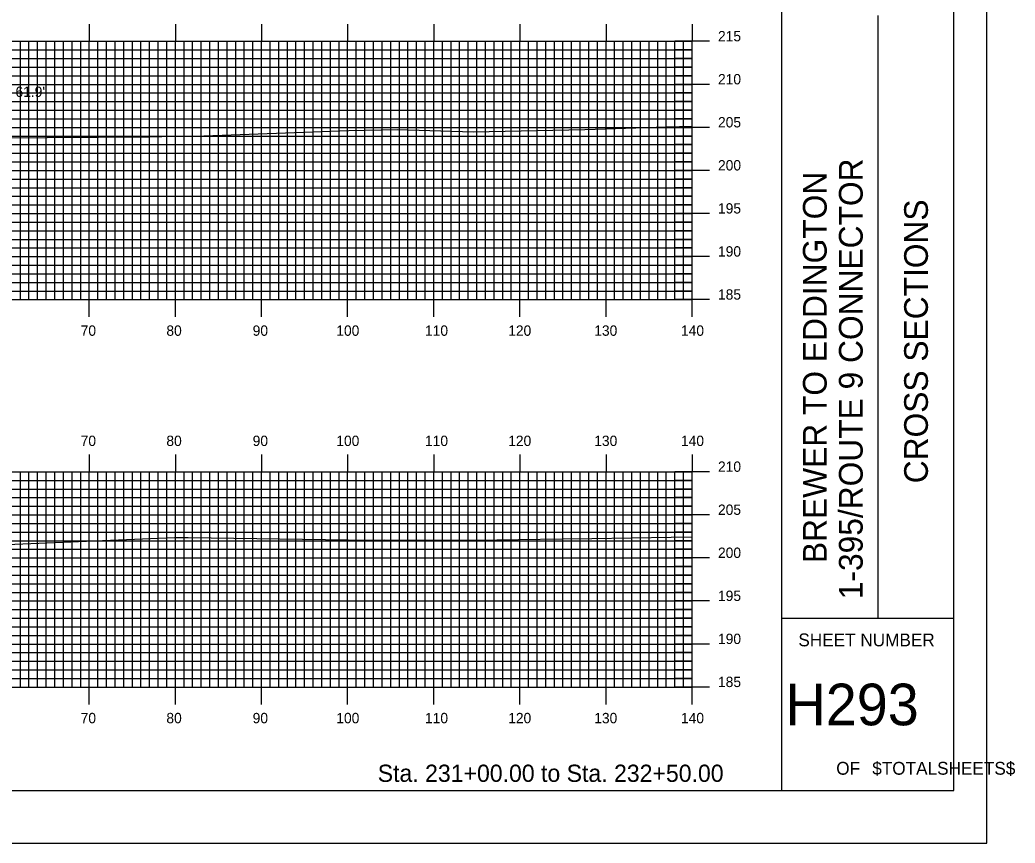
# Model space of a CAD drawing. Extents: x 1799568 to 1799912, y 442591 to 442811.
# Drawn here: x 1799796 to 1799911.5, y 442590.5 to 442686.2 of the extents above; entities that cross this region are included whole.
import ezdxf

# ---------------------------------------------------------------- set-up
doc = ezdxf.new("R2010")
doc.units = 0
for name, color, linetype in [('BORDER', 7, 'Continuous'), ('D_Text_Standard', 7, 'Continuous'), ('H_V ANNOTATION', 7, 'Continuous'), ('MAJOR', 7, 'Continuous'), ('MINOR', 7, 'Continuous'), ('PLOT BOUNDARY', 7, 'Continuous'), ('S_Roadway_Centerline', 7, 'Continuous')]:
    doc.layers.add(name, color=color, linetype=linetype)

msp = doc.modelspace()

# ---------------------------------------------------------------- linework, layer by layer
at = {"layer": 'BORDER'}
for p, q in [((1799884.41, 442596.67), (1799884.41, 442806.67)), ((1799895.59, 442616.67), (1799895.59, 442686.67)), ((1799884.41, 442616.67), (1799904.41, 442616.67))]:
    msp.add_line(p, q, dxfattribs=at)
msp.add_lwpolyline([(1799584.41, 442596.67), (1799904.41, 442596.67), (1799904.41, 442806.67), (1799584.41, 442806.67)], close=True, dxfattribs=at)
at = {"layer": 'MAJOR'}
for p, q in [((1799804.01, 442685.67), (1799804.01, 442683.67)), ((1799814.01, 442685.67), (1799814.01, 442683.67)), ((1799824.01, 442685.67), (1799824.01, 442683.67)), ((1799834.01, 442685.67), (1799834.01, 442683.67)), ((1799844.01, 442685.67), (1799844.01, 442683.67)), ((1799854.01, 442685.67), (1799854.01, 442683.67)), ((1799864.01, 442685.67), (1799864.01, 442683.67)), ((1799874.01, 442685.67), (1799874.01, 442683.67)), ((1799594.01, 442683.67), (1799874.01, 442683.67)), ((1799594.01, 442683.67), (1799874.01, 442683.67)), ((1799804.01, 442653.67), (1799804.01, 442683.67)), ((1799814.01, 442653.67), (1799814.01, 442683.67)), ((1799824.01, 442653.67), (1799824.01, 442683.67)), ((1799834.01, 442653.67), (1799834.01, 442683.67)), ((1799844.01, 442653.67), (1799844.01, 442683.67)), ((1799854.01, 442653.67), (1799854.01, 442683.67)), ((1799864.01, 442653.67), (1799864.01, 442683.67)), ((1799876.01, 442683.67), (1799872.01, 442683.67)), ((1799874.01, 442653.67), (1799874.01, 442683.67)), ((1799874.01, 442653.67), (1799874.01, 442683.67)), ((1799594.01, 442678.67), (1799874.01, 442678.67)), ((1799876.01, 442678.67), (1799872.01, 442678.67)), ((1799594.01, 442673.67), (1799874.01, 442673.67)), ((1799876.01, 442673.67), (1799872.01, 442673.67)), ((1799594.01, 442668.67), (1799874.01, 442668.67)), ((1799876.01, 442668.67), (1799872.01, 442668.67)), ((1799594.01, 442663.67), (1799874.01, 442663.67)), ((1799876.01, 442663.67), (1799872.01, 442663.67)), ((1799594.01, 442658.67), (1799874.01, 442658.67)), ((1799876.01, 442658.67), (1799872.01, 442658.67)), ((1799594.01, 442653.67), (1799874.01, 442653.67)), ((1799594.01, 442653.67), (1799874.01, 442653.67)), ((1799804.01, 442651.66), (1799804.01, 442653.67)), ((1799814.01, 442651.66), (1799814.01, 442653.67)), ((1799824.01, 442651.66), (1799824.01, 442653.67)), ((1799834.01, 442651.66), (1799834.01, 442653.67)), ((1799844.01, 442651.66), (1799844.01, 442653.67)), ((1799854.01, 442651.66), (1799854.01, 442653.67)), ((1799864.01, 442651.66), (1799864.01, 442653.67)), ((1799876.01, 442653.67), (1799872.01, 442653.67)), ((1799874.01, 442651.66), (1799874.01, 442653.67)), ((1799804.01, 442635.67), (1799804.01, 442633.67)), ((1799814.01, 442635.67), (1799814.01, 442633.67)), ((1799824.01, 442635.67), (1799824.01, 442633.67)), ((1799834.01, 442635.67), (1799834.01, 442633.67)), ((1799844.01, 442635.67), (1799844.01, 442633.67)), ((1799854.01, 442635.67), (1799854.01, 442633.67)), ((1799864.01, 442635.67), (1799864.01, 442633.67)), ((1799874.01, 442635.67), (1799874.01, 442633.67)), ((1799594.01, 442633.67), (1799874.01, 442633.67)), ((1799594.01, 442633.67), (1799874.01, 442633.67)), ((1799804.01, 442608.67), (1799804.01, 442633.67)), ((1799814.01, 442608.67), (1799814.01, 442633.67)), ((1799824.01, 442608.67), (1799824.01, 442633.67)), ((1799834.01, 442608.67), (1799834.01, 442633.67)), ((1799844.01, 442608.67), (1799844.01, 442633.67)), ((1799854.01, 442608.67), (1799854.01, 442633.67)), ((1799864.01, 442608.67), (1799864.01, 442633.67)), ((1799876.01, 442633.67), (1799872.01, 442633.67)), ((1799874.01, 442608.67), (1799874.01, 442633.67)), ((1799874.01, 442608.67), (1799874.01, 442633.67)), ((1799594.01, 442628.67), (1799874.01, 442628.67)), ((1799876.01, 442628.67), (1799872.01, 442628.67)), ((1799594.01, 442623.67), (1799874.01, 442623.67)), ((1799876.01, 442623.67), (1799872.01, 442623.67)), ((1799594.01, 442618.67), (1799874.01, 442618.67)), ((1799876.01, 442618.67), (1799872.01, 442618.67)), ((1799594.01, 442613.67), (1799874.01, 442613.67)), ((1799876.01, 442613.67), (1799872.01, 442613.67)), ((1799594.01, 442608.67), (1799874.01, 442608.67)), ((1799594.01, 442608.67), (1799874.01, 442608.67)), ((1799804.01, 442606.66), (1799804.01, 442608.67)), ((1799814.01, 442606.66), (1799814.01, 442608.67)), ((1799824.01, 442606.66), (1799824.01, 442608.67)), ((1799834.01, 442606.66), (1799834.01, 442608.67)), ((1799844.01, 442606.66), (1799844.01, 442608.67)), ((1799854.01, 442606.66), (1799854.01, 442608.67)), ((1799864.01, 442606.66), (1799864.01, 442608.67)), ((1799876.01, 442608.67), (1799872.01, 442608.67)), ((1799874.01, 442606.66), (1799874.01, 442608.67))]:
    msp.add_line(p, q, dxfattribs=at)
at = {"layer": 'MINOR'}
for p, q in [((1799796.01, 442653.67), (1799796.01, 442683.67)), ((1799797.01, 442653.67), (1799797.01, 442683.67)), ((1799798.01, 442653.67), (1799798.01, 442683.67)), ((1799799.01, 442653.67), (1799799.01, 442683.67)), ((1799800.01, 442653.67), (1799800.01, 442683.67)), ((1799801.01, 442653.67), (1799801.01, 442683.67)), ((1799802.01, 442653.67), (1799802.01, 442683.67)), ((1799803.01, 442653.67), (1799803.01, 442683.67)), ((1799805.01, 442653.67), (1799805.01, 442683.67)), ((1799806.01, 442653.67), (1799806.01, 442683.67)), ((1799807.01, 442653.67), (1799807.01, 442683.67)), ((1799808.01, 442653.67), (1799808.01, 442683.67)), ((1799809.01, 442653.67), (1799809.01, 442683.67)), ((1799810.01, 442653.67), (1799810.01, 442683.67)), ((1799811.01, 442653.67), (1799811.01, 442683.67)), ((1799812.01, 442653.67), (1799812.01, 442683.67)), ((1799813.01, 442653.67), (1799813.01, 442683.67)), ((1799815.01, 442653.67), (1799815.01, 442683.67)), ((1799816.01, 442653.67), (1799816.01, 442683.67)), ((1799817.01, 442653.67), (1799817.01, 442683.67)), ((1799818.01, 442653.67), (1799818.01, 442683.67)), ((1799819.01, 442653.67), (1799819.01, 442683.67)), ((1799820.01, 442653.67), (1799820.01, 442683.67)), ((1799821.01, 442653.67), (1799821.01, 442683.67)), ((1799822.01, 442653.67), (1799822.01, 442683.67)), ((1799823.01, 442653.67), (1799823.01, 442683.67)), ((1799825.01, 442653.67), (1799825.01, 442683.67)), ((1799826.01, 442653.67), (1799826.01, 442683.67)), ((1799827.01, 442653.67), (1799827.01, 442683.67)), ((1799828.01, 442653.67), (1799828.01, 442683.67)), ((1799829.01, 442653.67), (1799829.01, 442683.67)), ((1799830.01, 442653.67), (1799830.01, 442683.67)), ((1799831.01, 442653.67), (1799831.01, 442683.67)), ((1799832.01, 442653.67), (1799832.01, 442683.67)), ((1799833.01, 442653.67), (1799833.01, 442683.67)), ((1799835.01, 442653.67), (1799835.01, 442683.67)), ((1799836.01, 442653.67), (1799836.01, 442683.67)), ((1799837.01, 442653.67), (1799837.01, 442683.67)), ((1799838.01, 442653.67), (1799838.01, 442683.67)), ((1799839.01, 442653.67), (1799839.01, 442683.67)), ((1799840.01, 442653.67), (1799840.01, 442683.67)), ((1799841.01, 442653.67), (1799841.01, 442683.67)), ((1799842.01, 442653.67), (1799842.01, 442683.67)), ((1799843.01, 442653.67), (1799843.01, 442683.67)), ((1799845.01, 442653.67), (1799845.01, 442683.67)), ((1799846.01, 442653.67), (1799846.01, 442683.67)), ((1799847.01, 442653.67), (1799847.01, 442683.67)), ((1799848.01, 442653.67), (1799848.01, 442683.67)), ((1799849.01, 442653.67), (1799849.01, 442683.67)), ((1799850.01, 442653.67), (1799850.01, 442683.67)), ((1799851.01, 442653.67), (1799851.01, 442683.67)), ((1799852.01, 442653.67), (1799852.01, 442683.67)), ((1799853.01, 442653.67), (1799853.01, 442683.67)), ((1799855.01, 442653.67), (1799855.01, 442683.67)), ((1799856.01, 442653.67), (1799856.01, 442683.67)), ((1799857.01, 442653.67), (1799857.01, 442683.67)), ((1799858.01, 442653.67), (1799858.01, 442683.67)), ((1799859.01, 442653.67), (1799859.01, 442683.67)), ((1799860.01, 442653.67), (1799860.01, 442683.67)), ((1799861.01, 442653.67), (1799861.01, 442683.67)), ((1799862.01, 442653.67), (1799862.01, 442683.67)), ((1799863.01, 442653.67), (1799863.01, 442683.67)), ((1799865.01, 442653.67), (1799865.01, 442683.67)), ((1799866.01, 442653.67), (1799866.01, 442683.67)), ((1799867.01, 442653.67), (1799867.01, 442683.67)), ((1799868.01, 442653.67), (1799868.01, 442683.67)), ((1799869.01, 442653.67), (1799869.01, 442683.67)), ((1799870.01, 442653.67), (1799870.01, 442683.67)), ((1799871.01, 442653.67), (1799871.01, 442683.67)), ((1799872.01, 442653.67), (1799872.01, 442683.67)), ((1799873.01, 442653.67), (1799873.01, 442683.67)), ((1799594.01, 442682.67), (1799874.01, 442682.67)), ((1799874.01, 442682.67), (1799872.01, 442682.67)), ((1799594.01, 442681.67), (1799874.01, 442681.67)), ((1799874.01, 442681.67), (1799872.01, 442681.67)), ((1799594.01, 442680.67), (1799874.01, 442680.67)), ((1799874.01, 442680.67), (1799872.01, 442680.67)), ((1799594.01, 442679.67), (1799874.01, 442679.67)), ((1799874.01, 442679.67), (1799872.01, 442679.67)), ((1799594.01, 442677.67), (1799874.01, 442677.67)), ((1799594.01, 442676.67), (1799874.01, 442676.67)), ((1799874.01, 442677.67), (1799872.01, 442677.67)), ((1799874.01, 442676.67), (1799872.01, 442676.67)), ((1799594.01, 442675.67), (1799874.01, 442675.67)), ((1799874.01, 442675.67), (1799872.01, 442675.67)), ((1799594.01, 442674.67), (1799874.01, 442674.67)), ((1799874.01, 442674.67), (1799872.01, 442674.67)), ((1799594.01, 442672.67), (1799874.01, 442672.67)), ((1799874.01, 442672.67), (1799872.01, 442672.67)), ((1799594.01, 442671.67), (1799874.01, 442671.67)), ((1799874.01, 442671.67), (1799872.01, 442671.67)), ((1799594.01, 442670.67), (1799874.01, 442670.67)), ((1799874.01, 442670.67), (1799872.01, 442670.67)), ((1799594.01, 442669.67), (1799874.01, 442669.67)), ((1799874.01, 442669.67), (1799872.01, 442669.67)), ((1799594.01, 442667.67), (1799874.01, 442667.67)), ((1799874.01, 442667.67), (1799872.01, 442667.67)), ((1799594.01, 442666.67), (1799874.01, 442666.67)), ((1799874.01, 442666.67), (1799872.01, 442666.67)), ((1799594.01, 442665.67), (1799874.01, 442665.67)), ((1799874.01, 442665.67), (1799872.01, 442665.67)), ((1799594.01, 442664.67), (1799874.01, 442664.67)), ((1799874.01, 442664.67), (1799872.01, 442664.67)), ((1799594.01, 442662.67), (1799874.01, 442662.67)), ((1799594.01, 442661.67), (1799874.01, 442661.67)), ((1799874.01, 442662.67), (1799872.01, 442662.67)), ((1799874.01, 442661.67), (1799872.01, 442661.67)), ((1799594.01, 442660.67), (1799874.01, 442660.67)), ((1799874.01, 442660.67), (1799872.01, 442660.67)), ((1799594.01, 442659.67), (1799874.01, 442659.67)), ((1799874.01, 442659.67), (1799872.01, 442659.67)), ((1799594.01, 442657.67), (1799874.01, 442657.67)), ((1799874.01, 442657.67), (1799872.01, 442657.67)), ((1799594.01, 442656.67), (1799874.01, 442656.67)), ((1799874.01, 442656.67), (1799872.01, 442656.67)), ((1799594.01, 442655.67), (1799874.01, 442655.67)), ((1799874.01, 442655.67), (1799872.01, 442655.67)), ((1799594.01, 442654.67), (1799874.01, 442654.67)), ((1799874.01, 442654.67), (1799872.01, 442654.67)), ((1799796.01, 442608.67), (1799796.01, 442633.67)), ((1799797.01, 442608.67), (1799797.01, 442633.67)), ((1799798.01, 442608.67), (1799798.01, 442633.67)), ((1799799.01, 442608.67), (1799799.01, 442633.67)), ((1799800.01, 442608.67), (1799800.01, 442633.67)), ((1799801.01, 442608.67), (1799801.01, 442633.67)), ((1799802.01, 442608.67), (1799802.01, 442633.67)), ((1799803.01, 442608.67), (1799803.01, 442633.67)), ((1799805.01, 442608.67), (1799805.01, 442633.67)), ((1799806.01, 442608.67), (1799806.01, 442633.67)), ((1799807.01, 442608.67), (1799807.01, 442633.67)), ((1799808.01, 442608.67), (1799808.01, 442633.67)), ((1799809.01, 442608.67), (1799809.01, 442633.67)), ((1799810.01, 442608.67), (1799810.01, 442633.67)), ((1799811.01, 442608.67), (1799811.01, 442633.67)), ((1799812.01, 442608.67), (1799812.01, 442633.67)), ((1799813.01, 442608.67), (1799813.01, 442633.67)), ((1799815.01, 442608.67), (1799815.01, 442633.67)), ((1799816.01, 442608.67), (1799816.01, 442633.67)), ((1799817.01, 442608.67), (1799817.01, 442633.67)), ((1799818.01, 442608.67), (1799818.01, 442633.67)), ((1799819.01, 442608.67), (1799819.01, 442633.67)), ((1799820.01, 442608.67), (1799820.01, 442633.67)), ((1799821.01, 442608.67), (1799821.01, 442633.67)), ((1799822.01, 442608.67), (1799822.01, 442633.67)), ((1799823.01, 442608.67), (1799823.01, 442633.67)), ((1799825.01, 442608.67), (1799825.01, 442633.67)), ((1799826.01, 442608.67), (1799826.01, 442633.67)), ((1799827.01, 442608.67), (1799827.01, 442633.67)), ((1799828.01, 442608.67), (1799828.01, 442633.67)), ((1799829.01, 442608.67), (1799829.01, 442633.67)), ((1799830.01, 442608.67), (1799830.01, 442633.67)), ((1799831.01, 442608.67), (1799831.01, 442633.67)), ((1799832.01, 442608.67), (1799832.01, 442633.67)), ((1799833.01, 442608.67), (1799833.01, 442633.67)), ((1799835.01, 442608.67), (1799835.01, 442633.67)), ((1799836.01, 442608.67), (1799836.01, 442633.67)), ((1799837.01, 442608.67), (1799837.01, 442633.67)), ((1799838.01, 442608.67), (1799838.01, 442633.67)), ((1799839.01, 442608.67), (1799839.01, 442633.67)), ((1799840.01, 442608.67), (1799840.01, 442633.67)), ((1799841.01, 442608.67), (1799841.01, 442633.67)), ((1799842.01, 442608.67), (1799842.01, 442633.67)), ((1799843.01, 442608.67), (1799843.01, 442633.67)), ((1799845.01, 442608.67), (1799845.01, 442633.67)), ((1799846.01, 442608.67), (1799846.01, 442633.67)), ((1799847.01, 442608.67), (1799847.01, 442633.67)), ((1799848.01, 442608.67), (1799848.01, 442633.67)), ((1799849.01, 442608.67), (1799849.01, 442633.67)), ((1799850.01, 442608.67), (1799850.01, 442633.67)), ((1799851.01, 442608.67), (1799851.01, 442633.67)), ((1799852.01, 442608.67), (1799852.01, 442633.67)), ((1799853.01, 442608.67), (1799853.01, 442633.67)), ((1799855.01, 442608.67), (1799855.01, 442633.67)), ((1799856.01, 442608.67), (1799856.01, 442633.67)), ((1799857.01, 442608.67), (1799857.01, 442633.67)), ((1799858.01, 442608.67), (1799858.01, 442633.67)), ((1799859.01, 442608.67), (1799859.01, 442633.67)), ((1799860.01, 442608.67), (1799860.01, 442633.67)), ((1799861.01, 442608.67), (1799861.01, 442633.67)), ((1799862.01, 442608.67), (1799862.01, 442633.67)), ((1799863.01, 442608.67), (1799863.01, 442633.67)), ((1799865.01, 442608.67), (1799865.01, 442633.67)), ((1799866.01, 442608.67), (1799866.01, 442633.67)), ((1799867.01, 442608.67), (1799867.01, 442633.67)), ((1799868.01, 442608.67), (1799868.01, 442633.67)), ((1799869.01, 442608.67), (1799869.01, 442633.67)), ((1799870.01, 442608.67), (1799870.01, 442633.67)), ((1799871.01, 442608.67), (1799871.01, 442633.67)), ((1799872.01, 442608.67), (1799872.01, 442633.67)), ((1799873.01, 442608.67), (1799873.01, 442633.67)), ((1799594.01, 442632.67), (1799874.01, 442632.67)), ((1799594.01, 442631.67), (1799874.01, 442631.67)), ((1799874.01, 442632.67), (1799872.01, 442632.67)), ((1799874.01, 442631.67), (1799872.01, 442631.67)), ((1799594.01, 442630.67), (1799874.01, 442630.67)), ((1799874.01, 442630.67), (1799872.01, 442630.67)), ((1799594.01, 442629.67), (1799874.01, 442629.67)), ((1799874.01, 442629.67), (1799872.01, 442629.67)), ((1799594.01, 442627.67), (1799874.01, 442627.67)), ((1799874.01, 442627.67), (1799872.01, 442627.67)), ((1799594.01, 442626.67), (1799874.01, 442626.67)), ((1799874.01, 442626.67), (1799872.01, 442626.67)), ((1799594.01, 442625.67), (1799874.01, 442625.67)), ((1799594.01, 442624.67), (1799874.01, 442624.67)), ((1799874.01, 442625.67), (1799872.01, 442625.67)), ((1799874.01, 442624.67), (1799872.01, 442624.67)), ((1799594.01, 442622.67), (1799874.01, 442622.67)), ((1799874.01, 442622.67), (1799872.01, 442622.67)), ((1799594.01, 442621.67), (1799874.01, 442621.67)), ((1799874.01, 442621.67), (1799872.01, 442621.67)), ((1799594.01, 442620.67), (1799874.01, 442620.67)), ((1799874.01, 442620.67), (1799872.01, 442620.67)), ((1799594.01, 442619.67), (1799874.01, 442619.67)), ((1799874.01, 442619.67), (1799872.01, 442619.67)), ((1799594.01, 442617.67), (1799874.01, 442617.67)), ((1799594.01, 442616.67), (1799874.01, 442616.67)), ((1799874.01, 442617.67), (1799872.01, 442617.67)), ((1799874.01, 442616.67), (1799872.01, 442616.67)), ((1799594.01, 442615.67), (1799874.01, 442615.67)), ((1799874.01, 442615.67), (1799872.01, 442615.67)), ((1799594.01, 442614.67), (1799874.01, 442614.67)), ((1799874.01, 442614.67), (1799872.01, 442614.67)), ((1799594.01, 442612.67), (1799874.01, 442612.67)), ((1799874.01, 442612.67), (1799872.01, 442612.67)), ((1799594.01, 442611.67), (1799874.01, 442611.67)), ((1799874.01, 442611.67), (1799872.01, 442611.67)), ((1799594.01, 442610.67), (1799874.01, 442610.67)), ((1799594.01, 442609.67), (1799874.01, 442609.67)), ((1799874.01, 442610.67), (1799872.01, 442610.67)), ((1799874.01, 442609.67), (1799872.01, 442609.67))]:
    msp.add_line(p, q, dxfattribs=at)
at = {"layer": 'PLOT BOUNDARY'}
msp.add_lwpolyline([(1799568.22, 442590.55), (1799908.22, 442590.55), (1799908.22, 442810.55), (1799568.22, 442810.55)], close=True, dxfattribs=at)
at = {"layer": 'S_Roadway_Centerline'}
for points in [[(1799793.12, 442672.45), (1799811.05, 442672.58), (1799813.84, 442672.64), (1799816.28, 442672.65), (1799834.15, 442673.33), (1799839.79, 442673.43), (1799848.6, 442673.17), (1799861.54, 442673.44), (1799871.04, 442673.72), (1799874.01, 442673.82)], [(1799791.61, 442625.13), (1799813.9, 442626.06), (1799815.48, 442626.06), (1799836.72, 442625.75), (1799838.27, 442625.76), (1799848.79, 442625.74), (1799858.93, 442625.88), (1799862.38, 442625.91), (1799871.59, 442626.09), (1799874.01, 442626.1)]]:
    msp.add_lwpolyline(points, dxfattribs=at)

# ---------------------------------------------------------------- texts
at = {"layer": 'BORDER'}
for s, p in [('1-395/ROUTE 9 CONNECTOR', (1799893.81, 442618.87)), ('BREWER TO EDDINGTON', (1799889.63, 442623.07)), ('CROSS SECTIONS', (1799901.38, 442632.34))]:
    msp.add_text(s, height=2.7557, rotation=90, dxfattribs=at).set_placement(p)
for s, height, p in [('SHEET NUMBER', 1.4905, (1799886.34, 442613.4)), ('H293', 4.839, (1799884.85, 442604.23)), ('OF', 1.491, (1799890.74, 442598.49)), ('$TOTALSHEETS$', 1.4905, (1799894.92, 442598.49))]:
    msp.add_text(s, height=height, dxfattribs=at).set_placement(p)
at = {"layer": 'D_Text_Standard'}
msp.add_text("61.9'", height=1.2, dxfattribs=at).set_placement((1799795.44, 442677.21))
at = {"layer": 'H_V ANNOTATION'}
for s, height, p in [('215', 1.2, (1799877.01, 442683.67)), ('210', 1.2, (1799877.01, 442678.67)), ('205', 1.2, (1799877.01, 442673.67)), ('200', 1.2, (1799877.01, 442668.67)), ('195', 1.2, (1799877.01, 442663.67)), ('190', 1.2, (1799877.01, 442658.67)), ('185', 1.2, (1799877.01, 442653.67)), ('70', 1.2, (1799803.01, 442649.47)), ('80', 1.2, (1799812.96, 442649.47)), ('90', 1.2, (1799822.98, 442649.47)), ('100', 1.2, (1799832.69, 442649.47)), ('110', 1.2, (1799842.99, 442649.47)), ('120', 1.2, (1799852.65, 442649.47)), ('130', 1.2, (1799862.64, 442649.47)), ('140', 1.2, (1799872.71, 442649.47)), ('70', 1.2, (1799803.01, 442636.67)), ('80', 1.2, (1799812.96, 442636.67)), ('90', 1.2, (1799822.98, 442636.67)), ('100', 1.2, (1799832.69, 442636.67)), ('110', 1.2, (1799842.99, 442636.67)), ('120', 1.2, (1799852.65, 442636.67)), ('130', 1.2, (1799862.64, 442636.67)), ('140', 1.2, (1799872.71, 442636.67)), ('210', 1.2, (1799877.01, 442633.67)), ('205', 1.2, (1799877.01, 442628.67)), ('200', 1.2, (1799877.01, 442623.67)), ('195', 1.2, (1799877.01, 442618.67)), ('190', 1.2, (1799877.01, 442613.67)), ('185', 1.2, (1799877.01, 442608.67)), ('70', 1.2, (1799803.01, 442604.47)), ('80', 1.2, (1799812.96, 442604.47)), ('90', 1.2, (1799822.98, 442604.47)), ('100', 1.2, (1799832.69, 442604.47)), ('110', 1.2, (1799842.99, 442604.47)), ('120', 1.2, (1799852.65, 442604.47)), ('130', 1.2, (1799862.64, 442604.47)), ('140', 1.2, (1799872.71, 442604.47)), ('Sta. 231+00.00 to Sta. 232+50.00', 2.0004, (1799837.5, 442597.66))]:
    msp.add_text(s, height=height, dxfattribs=at).set_placement(p)

doc.saveas('drawing.dxf')
